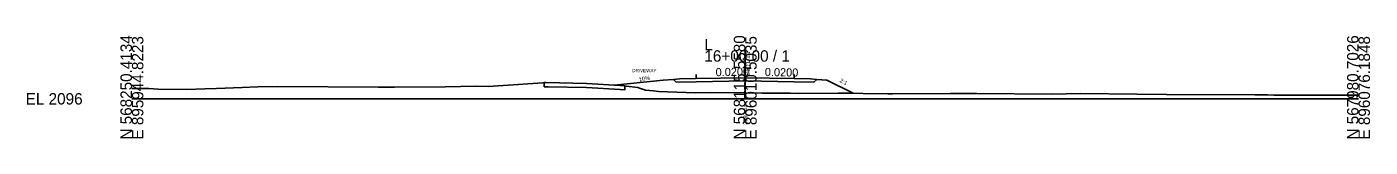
# Model space of a CAD drawing. Extents: x -26 to 1603, y -10 to 13527.
# Drawn here: x -25.7 to 302.8, y 3490.3 to 3515.5 of the extents above; entities that cross this region are included whole.
import ezdxf

# ---------------------------------------------------------------- set-up
doc = ezdxf.new("R2010")
doc.units = 0
for name, color, linetype in [('Default', 7, 'Continuous'), ('Exist XS Center Line Elevation Label', 7, 'Continuous'), ('Exist XS Ground Line', 7, 'Continuous'), ('Old_Level_61', 7, 'Continuous'), ('Old_Level_63', 7, 'Continuous'), ('Prop XS Ditch Standard Text', 7, 'Continuous'), ('Prop XS Earthwork Shape', 7, 'Continuous'), ('Prop XS EOT Tick Mark', 7, 'Continuous'), ('Prop XS Finish Grade', 7, 'Continuous'), ('Prop XS Finish Grade Earthwork', 7, 'Continuous'), ('Prop XS Finish Grade Paved Shoulder', 7, 'Continuous'), ('Prop XS Finish Grade Pavement', 7, 'Continuous'), ('Prop XS Side Slope Text', 7, 'Continuous'), ('Prop XS Subgrade Earthwork', 7, 'Continuous'), ('Prop XSC Text', 7, 'Continuous')]:
    doc.layers.add(name, color=color, linetype=linetype)

msp = doc.modelspace()

# ---------------------------------------------------------------- linework, layer by layer
at = {"layer": 'Exist XS Ground Line'}
for p, q in [((0, 3502.51), (3.33, 3502.5)), ((3.33, 3502.5), (4.16, 3502.5)), ((4.16, 3502.5), (6.43, 3502.41)), ((6.43, 3502.41), (13.35, 3502.31)), ((13.35, 3502.31), (17.85, 3502.43)), ((17.85, 3502.43), (20.65, 3502.54)), ((20.65, 3502.54), (26.99, 3502.8)), ((26.99, 3502.8), (30.79, 3502.91)), ((30.79, 3502.91), (35.67, 3503.02)), ((35.67, 3503.02), (60.23, 3502.88)), ((60.23, 3502.88), (64.25, 3502.9)), ((64.25, 3502.9), (76.65, 3502.91)), ((76.65, 3502.91), (84.19, 3503.09)), ((84.19, 3503.09), (87.17, 3503.04)), ((87.17, 3503.04), (90.77, 3503.28)), ((90.77, 3503.28), (100.51, 3503.94)), ((100.51, 3503.94), (100.82, 3503.97)), ((100.82, 3503.97), (101.24, 3503.97)), ((101.24, 3503.97), (111.16, 3503.78)), ((111.16, 3503.78), (119.43, 3503.25)), ((119.43, 3503.25), (120.56, 3503.19)), ((120.56, 3503.19), (120.92, 3503.14)), ((120.92, 3503.14), (123.76, 3502.81)), ((123.76, 3502.81), (124.12, 3502.62)), ((124.12, 3502.62), (125.58, 3502.14)), ((125.58, 3502.14), (127.58, 3501.93)), ((127.58, 3501.93), (128.76, 3501.78)), ((128.76, 3501.78), (130.98, 3501.7)), ((130.98, 3501.7), (137.86, 3501.47)), ((137.86, 3501.47), (141.63, 3501.58)), ((141.63, 3501.58), (150, 3501.44)), ((150, 3501.44), (154.17, 3501.37)), ((154.17, 3501.37), (158.62, 3501.4)), ((158.62, 3501.4), (161.1, 3501.35)), ((161.1, 3501.35), (163.03, 3501.32)), ((163.03, 3501.32), (172.73, 3501.39)), ((172.73, 3501.39), (184.92, 3501.24)), ((184.92, 3501.24), (186.05, 3501.23)), ((186.05, 3501.23), (200.19, 3501.3)), ((200.19, 3501.3), (206.65, 3501.31)), ((206.65, 3501.31), (224.99, 3501.18)), ((224.99, 3501.18), (231.98, 3501.27)), ((231.98, 3501.27), (245.79, 3501.18)), ((245.79, 3501.18), (253.04, 3501.07)), ((253.04, 3501.07), (274.68, 3500.97)), ((274.68, 3500.97), (277.78, 3500.95)), ((277.78, 3500.95), (279.29, 3500.9)), ((279.29, 3500.9), (300, 3500.86))]:
    msp.add_line(p, q, dxfattribs=at)
at = {"layer": 'Old_Level_61'}
for p, q in [((100.82, 3503.97), (100.82, 3502.97)), ((100.82, 3502.97), (101.24, 3502.97)), ((100.82, 3502.97), (100.82, 3502.97)), ((101.24, 3502.97), (101.83, 3502.96)), ((101.83, 3502.96), (111.16, 3502.78)), ((111.16, 3502.78), (119.43, 3502.25)), ((119.43, 3502.25), (120.56, 3502.19)), ((120.56, 3502.19), (120.56, 3503.19)), ((120.56, 3502.19), (120.56, 3502.19))]:
    msp.add_line(p, q, dxfattribs=at)
at = {"layer": 'Old_Level_63'}
for p, q in [((150, 3500), (150, 3511.92)), ((0, 3500), (150, 3500)), ((150, 3500), (300, 3500))]:
    msp.add_line(p, q, dxfattribs=at)
at = {"layer": 'Prop XS Earthwork Shape'}
msp.add_lwpolyline([(133.15, 3504.06), (132.46, 3504.75), (129.93, 3504.55), (117.91, 3503.35), (119.43, 3503.25), (120.56, 3503.19), (120.92, 3503.14), (123.76, 3502.81), (124.12, 3502.62), (125.58, 3502.14), (127.58, 3501.93), (128.76, 3501.78), (130.98, 3501.7), (137.86, 3501.47), (141.63, 3501.58), (150, 3501.44), (154.17, 3501.37), (158.62, 3501.4), (161.1, 3501.35), (163.03, 3501.32), (172.73, 3501.39), (176.41, 3501.35), (170, 3504.55), (167.5, 3504.75), (166.81, 3504.06), (162, 3504.16), (150, 3504.4), (138, 3504.16)], close=True, dxfattribs=at)
at = {"layer": 'Prop XS EOT Tick Mark'}
for p, q in [((138, 3504.95), (138, 3505.95)), ((162, 3504.95), (162, 3505.95))]:
    msp.add_line(p, q, dxfattribs=at)
at = {"layer": 'Prop XS Finish Grade'}
for p, q in [((133.96, 3504.87), (132.46, 3504.75)), ((166, 3504.87), (167.5, 3504.75))]:
    msp.add_line(p, q, dxfattribs=at)
at = {"layer": 'Prop XS Finish Grade Earthwork'}
for p, q in [((129.93, 3504.55), (117.91, 3503.35)), ((132.46, 3504.75), (129.93, 3504.55)), ((167.5, 3504.75), (170, 3504.55)), ((170, 3504.55), (176.41, 3501.35))]:
    msp.add_line(p, q, dxfattribs=at)
at = {"layer": 'Prop XS Finish Grade Paved Shoulder'}
for p, q in [((138, 3504.95), (133.96, 3504.87)), ((162, 3504.95), (166, 3504.87))]:
    msp.add_line(p, q, dxfattribs=at)
at = {"layer": 'Prop XS Finish Grade Pavement'}
for p, q in [((138, 3504.95), (150, 3505.19)), ((150, 3505.19), (162, 3504.95))]:
    msp.add_line(p, q, dxfattribs=at)
at = {"layer": 'Prop XS Subgrade Earthwork'}
for p, q in [((133.15, 3504.06), (132.46, 3504.75)), ((138, 3504.16), (133.15, 3504.06)), ((150, 3504.4), (138, 3504.16)), ((162, 3504.16), (150, 3504.4)), ((162, 3504.16), (166.81, 3504.06)), ((166.81, 3504.06), (167.5, 3504.75))]:
    msp.add_line(p, q, dxfattribs=at)

# ---------------------------------------------------------------- texts
at = {"layer": 'Default'}
for rotation, p in [(1.1458, (142.78, 3505.54)), (358.8542, (154.78, 3505.6))]:
    msp.add_text('0.0200', height=2, rotation=rotation, dxfattribs=at).set_placement(p)
at = {"layer": 'Exist XS Center Line Elevation Label'}
msp.add_text('2097.44', height=1, rotation=90, dxfattribs=at).set_placement((150.5, 3493.63))
at = {"layer": 'Old_Level_63'}
for s, p in [('N 568250.4134', (0, 3490)), ('N 568115.5580', (150, 3490)), ('N 567980.7026', (300, 3490)), ('E 895944.8223', (2.8, 3490)), ('E 896010.5035', (152.8, 3490)), ('E 896076.1848', (302.8, 3490))]:
    msp.add_text(s, height=2.8, rotation=90, dxfattribs=at).set_placement(p)
for s, p in [('16+00.00 / 1', (140, 3509.12)), ('L', (140, 3511.92)), ('EL 2096', (-26, 3498.6))]:
    msp.add_text(s, height=2.8, dxfattribs=at).set_placement(p)
at = {"layer": 'Prop XS Ditch Standard Text'}
msp.add_text('DRIVEWAY', height=0.8, dxfattribs=at).set_placement((122.39, 3506.54))
msp.add_text('10%', height=1, rotation=10.0122, dxfattribs=at).set_placement((124.06, 3504.23))
at = {"layer": 'Prop XS Side Slope Text'}
msp.add_text('2:1', height=1, rotation=333.4349, dxfattribs=at).set_placement((172.98, 3504.18))
at = {"layer": 'Prop XSC Text'}
msp.add_text(' 2101.19', height=1.2, rotation=90, dxfattribs=at).set_placement((151.2, 3505.19))

doc.saveas('drawing.dxf')
